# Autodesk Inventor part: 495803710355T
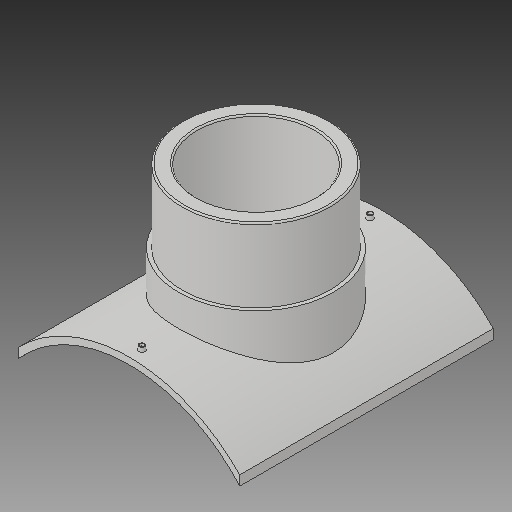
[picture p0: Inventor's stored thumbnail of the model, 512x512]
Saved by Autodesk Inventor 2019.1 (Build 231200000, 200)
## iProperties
Created: 2017-10
Part Number: 495803710355T
Material: Generic
Description: PLASSON BRANCH SADDLE  710x355
Document SubType Name: Modeling
Designer: KIM
Mass: 2754.05 g
Surface Area: 3037.44 cm^2
Volume: 2754.05 cm^3
Density: 1 g/cm^3
Appearance: Default
Author: KIM
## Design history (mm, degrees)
derived "495803.ipt"
feature "Solid1::495803.ipt"
tag "TaggingFeature1"
body "Solid1"
other parameters: "d1" = 16, "d2" = 532, "d4" = 0, "d12" = 380.6, "d13" = 14, "d14" = 274.5, "d16" = 5 deg, "d18" = 4, "d19" = 14, "d20" = 0, "d21" = 3, "d22" = 0, "d23" = 623, "d24" = 372.75, "d25" = 16, "d26" = 284, "d28" = 0, "d29" = 9.6, "d31" = 0, "d32" = 126, "d33" = 0, "d34" = 7.1, "d36" = 355, "d37" = 176.4, "d38" = 0, "d39" = 3.55, "d_1" = 355, "B_" = 532, "H_" = 252, "x_" = 16, "D_" = 16
